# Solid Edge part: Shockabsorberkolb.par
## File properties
Author: Türk
Template: Iso Part.par
Last saved by: Türk
Revision: 19
Application: Solid Edge
Accuracy: 0,990
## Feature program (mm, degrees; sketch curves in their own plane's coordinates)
pattern "PatternOccurrence_2"  XOffset = 18 deg
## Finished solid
Body 1: solid body, 86 faces, 166 edges, 0 vertices.
  Faces by surface: cylinder 82, plane 2, torus 2
  Edges by curve: circle 166
Bounding box of the edges (mm; curved faces can reach further): 40.000 x 20.000 x 40.000, from (-20, 0, -20) to (20, 20, 20).
Cylindrical faces by radius (mm): R1 x80, R5.5 x1, R20 x1
Toroidal faces (ring radius, tube radius in mm): R19.5 r0.5 x2
Planar faces by outward normal: +y 1, -y 1
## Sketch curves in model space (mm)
circle centre (0, 20, 0) radius 19.5
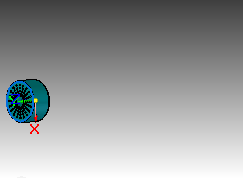
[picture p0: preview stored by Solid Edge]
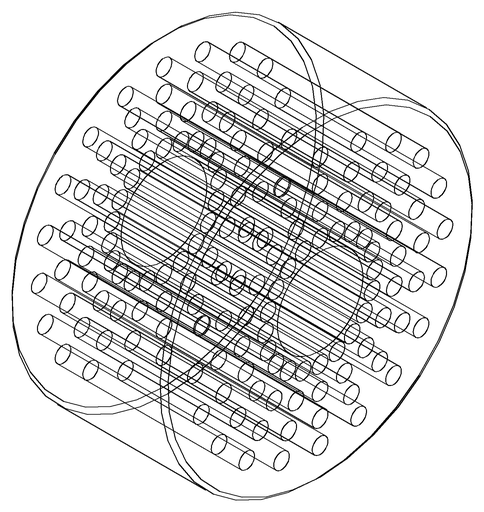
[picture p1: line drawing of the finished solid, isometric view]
